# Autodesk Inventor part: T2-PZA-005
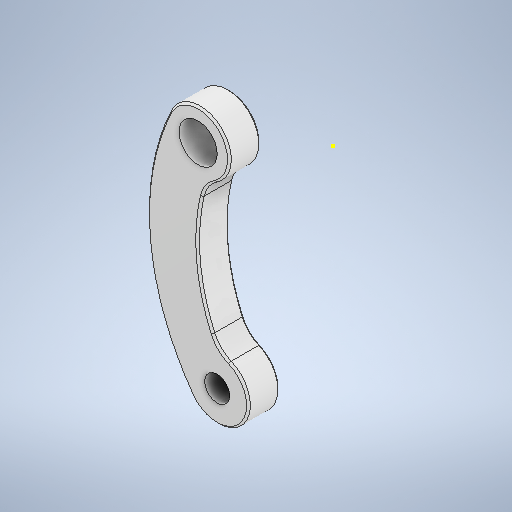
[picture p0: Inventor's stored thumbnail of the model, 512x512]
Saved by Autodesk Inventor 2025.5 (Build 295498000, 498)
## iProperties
Created: 2026-10
Part Number: T2-PZA-005
Material: Genérico
Description: Biela motriz
Document SubType Name: Modeling
Designer: Luis MuÃ±oz
Density: 1 g/cm^3
Appearance: Valor por defecto
Project: TESIS 2 - Plataforma mecatrÃ³nica preventiva desacoplada
Sending System: ONSHAPE BY PTC INC, 1.194
Preprocessor: ST-DEVELOPER v20
Material_Fabricacion: PLA
Title: Biela motriz
Revision Number: 00
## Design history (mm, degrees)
feature "Driving_Rod"
sketch "Boceto1"
  geometry: C1 r 5.488 at (-28.221, -16.127); 1 further point
  constraints: 1 centre point
sketch "Boceto2"
  geometry: 1 further point
extrude "Extrusión1" cut sketch "Boceto1" distance "d0" = 3.75; taper "d1" = 0 deg
node "Sólido1"
